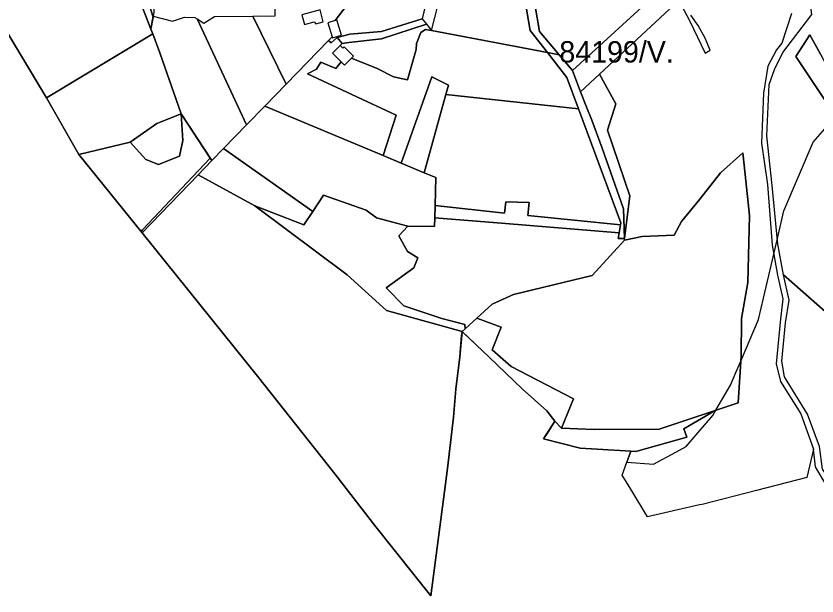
# Model space of a CAD drawing. Extents: x -477304 to -465429, y -1159113 to -1149210.
# Drawn here: x -474702 to -474140, y -1158012 to -1157605 of the extents above; entities that cross this region are included whole.
import ezdxf

# ---------------------------------------------------------------- set-up
doc = ezdxf.new("R2010")
doc.units = 0
for name, color, linetype in [('BPEJ_s', 7, 'Continuous'), ('PUPFL_s', 7, 'Continuous'), ('trav_porost_s', 7, 'Continuous')]:
    doc.layers.add(name, color=color, linetype=linetype)

msp = doc.modelspace()

# ---------------------------------------------------------------- linework, layer by layer
at = {"layer": 'BPEJ_s'}
for p, q in [((-474390.2, -1157843.79), (-474388.88, -1157828.71)), ((-474387.45, -1157827.13), (-474369.68, -1157843.95))]:
    msp.add_line(p, q, dxfattribs=at)
for points in [[(-474712.47, -1157608.26), (-474680.22, -1157661.92), (-474657.54, -1157701.76), (-474613, -1157756.78), (-474613.86, -1157755.71), (-474612.74, -1157754.54), (-474581.44, -1157721.26), (-474565.43, -1157704.24), (-474585.67, -1157673.2), (-474600.56, -1157630.43), (-474605.66, -1157617.09), (-474606.99, -1157613.7), (-474605.39, -1157605.33), (-474610.97, -1157587.24)], [(-474610.97, -1157587.24), (-474605.39, -1157605.33), (-474606.99, -1157613.7), (-474605.66, -1157617.09), (-474600.56, -1157630.43), (-474585.67, -1157673.2), (-474565.43, -1157704.24), (-474581.44, -1157721.26), (-474612.74, -1157754.54), (-474613.86, -1157755.71), (-474613, -1157756.78), (-474532.23, -1157857.36), (-474477.75, -1157925.91), (-474449.03, -1157963.01), (-474410.42, -1158011.51), (-474401.55, -1157943.6), (-474398.88, -1157921.94), (-474394.56, -1157886.06), (-474392.98, -1157866.44), (-474390.2, -1157843.79)], [(-474369.68, -1157843.95), (-474346.33, -1157866.24), (-474329.23, -1157881.6), (-474323.47, -1157888.85), (-474328.97, -1157897.46), (-474331.45, -1157901.34), (-474305.63, -1157907.68), (-474274.04, -1157909.6), (-474270.26, -1157909.83), (-474272.97, -1157917.53), (-474272.96, -1157917.53), (-474254.28, -1157919.03), (-474238.62, -1157910.51), (-474231.42, -1157906.59), (-474222.89, -1157896.69), (-474212.76, -1157884.93), (-474210.52, -1157881.1), (-474200.33, -1157863.66), (-474196.45, -1157854.58), (-474193.11, -1157846.74), (-474180.67, -1157817.53), (-474169.9, -1157771.55), (-474167.35, -1157760.68), (-474162.82, -1157741.31), (-474142.35, -1157693.16), (-474127.51, -1157676.31)], [(-474117.61, -1157959.68), (-474140.54, -1157920.94), (-474142.02, -1157908.41), (-474146.82, -1157928.48), (-474182.11, -1157937.48), (-474220.24, -1157947.2), (-474221.95, -1157947.64), (-474258.41, -1157955.89), (-474270.23, -1157936.46), (-474276.18, -1157926.68), (-474272.97, -1157917.53), (-474272.96, -1157917.53), (-474254.28, -1157919.03), (-474238.62, -1157910.51), (-474231.42, -1157906.59), (-474222.89, -1157896.69), (-474212.76, -1157884.93), (-474210.52, -1157881.1), (-474200.33, -1157863.66), (-474196.45, -1157854.58), (-474193.11, -1157846.74), (-474180.67, -1157817.53), (-474169.9, -1157771.55), (-474167.35, -1157760.68), (-474162.82, -1157741.31), (-474142.35, -1157693.16), (-474127.51, -1157676.31)], [(-474388.88, -1157828.71), (-474388.64, -1157826.01), (-474387.45, -1157827.13)]]:
    msp.add_lwpolyline(points, dxfattribs=at)
at = {"layer": 'PUPFL_s'}
for points in [[(-474712.47, -1157608.26), (-474722.74, -1157590.74), (-474760, -1157522.78), (-474710.53, -1157503.42), (-474659.13, -1157500.47), (-474645.25, -1157520.87), (-474636.26, -1157532.61), (-474626.39, -1157545.34), (-474617.6, -1157586.15), (-474606.99, -1157613.7), (-474605.66, -1157617.09), (-474680.22, -1157661.92)], [(-474607.95, -1157592.56), (-474605.02, -1157592.78), (-474604.85, -1157602.17), (-474605.28, -1157604.75), (-474606.99, -1157613.7), (-474617.6, -1157586.15), (-474626.39, -1157545.34), (-474636.26, -1157532.61), (-474645.25, -1157520.87), (-474633.94, -1157519.44), (-474631.77, -1157529.93), (-474617.59, -1157559.31), (-474616.84, -1157576.89)], [(-474605.66, -1157617.09), (-474600.56, -1157630.43), (-474585.67, -1157673.2), (-474602.64, -1157680.03), (-474621.38, -1157692.95), (-474657.54, -1157701.76), (-474680.22, -1157661.92)], [(-474320.52, -1157631.72), (-474311.11, -1157642.73), (-474305.4, -1157657.64), (-474301.46, -1157667.91), (-474297.65, -1157677.65), (-474290.32, -1157697.33), (-474275.38, -1157739.83), (-474274.67, -1157760.74), (-474278.99, -1157760.63), (-474278.39, -1157756.77), (-474277.5, -1157751.11), (-474277.29, -1157749.76), (-474306.96, -1157669.79), (-474315.19, -1157647.6), (-474328.71, -1157630.16)], [(-474290.32, -1157697.33), (-474297.65, -1157677.65), (-474301.46, -1157667.91), (-474305.4, -1157657.64), (-474292.29, -1157645.45), (-474280.73, -1157666.11), (-474286.53, -1157684.58), (-474270.81, -1157730.79), (-474274.67, -1157760.74), (-474275.38, -1157739.83)], [(-474573.77, -1157715.9), (-474613, -1157756.78), (-474657.54, -1157701.76), (-474621.38, -1157692.95), (-474610.44, -1157705.21), (-474601.68, -1157708.71), (-474586.74, -1157702.98), (-474584.53, -1157691.95), (-474585.67, -1157673.2), (-474564.28, -1157706.01)], [(-474601.68, -1157708.71), (-474610.44, -1157705.21), (-474621.38, -1157692.95), (-474602.64, -1157680.03), (-474585.67, -1157673.2), (-474584.53, -1157691.95), (-474586.74, -1157702.98)], [(-474555.93, -1157697.42), (-474493.38, -1157741.7), (-474499.53, -1157751.13), (-474533.93, -1157737.85), (-474573.77, -1157715.9), (-474564.28, -1157706.01)], [(-474388.64, -1157826.01), (-474390.2, -1157843.79), (-474392.98, -1157866.44), (-474394.56, -1157886.06), (-474398.88, -1157921.94), (-474401.55, -1157943.6), (-474410.42, -1158011.51), (-474449.03, -1157963.01), (-474477.75, -1157925.91), (-474532.23, -1157857.36), (-474613, -1157756.78), (-474573.77, -1157715.9), (-474533.93, -1157737.85), (-474469.31, -1157786.13), (-474441.6, -1157811.16)], [(-474448.65, -1157746.17), (-474426.68, -1157751.96), (-474432.98, -1157758.9), (-474426.97, -1157769.71), (-474419.65, -1157774.16), (-474422.39, -1157781.23), (-474441.83, -1157795.22), (-474429.47, -1157807.85), (-474402.86, -1157816.87), (-474386.7, -1157821.01), (-474386.44, -1157824.02), (-474388.64, -1157826.01), (-474441.6, -1157811.16), (-474469.31, -1157786.13), (-474533.93, -1157737.85), (-474499.53, -1157751.13), (-474493.38, -1157741.7), (-474485.88, -1157730.21), (-474455.86, -1157740.88)], [(-474429.47, -1157807.85), (-474441.83, -1157795.22), (-474422.39, -1157781.23), (-474419.65, -1157774.16), (-474426.97, -1157769.71), (-474432.98, -1157758.9), (-474426.68, -1157751.96), (-474407.92, -1157752.23), (-474407.77, -1157746.14), (-474358.18, -1157750.02), (-474278.39, -1157756.77), (-474278.99, -1157760.63), (-474274.67, -1157760.74), (-474274.63, -1157761.87), (-474297.39, -1157786.66), (-474352.58, -1157799.92), (-474367.39, -1157806.71), (-474378.32, -1157816.64), (-474386.44, -1157824.02), (-474386.7, -1157821.01), (-474402.86, -1157816.87)], [(-474146.32, -1157884.01), (-474162.34, -1157857.62), (-474164.23, -1157846.75), (-474161.58, -1157819.77), (-474159.1, -1157803.83), (-474163.09, -1157786.07), (-474116.35, -1157827.4), (-474076.57, -1157866.3), (-474078.2, -1157867.92), (-474084.04, -1157871.6), (-474096.65, -1157899.23), (-474108.02, -1157917.05), (-474129.83, -1157930.73), (-474135.71, -1157922.41), (-474137.72, -1157906.72)], [(-474318.78, -1157893.66), (-474323.47, -1157888.85), (-474329.23, -1157881.6), (-474346.33, -1157866.24), (-474369.68, -1157843.95), (-474388.64, -1157826.01), (-474386.44, -1157824.02), (-474378.32, -1157816.64), (-474361.24, -1157822.81), (-474367.57, -1157838.77), (-474354.16, -1157850.56), (-474310.37, -1157873.14)]]:
    msp.add_lwpolyline(points, close=True, dxfattribs=at)
at = {"layer": 'trav_porost_s'}
for points in [[(-474533.23, -1157555.32), (-474538.07, -1157546.35), (-474496.57, -1157551.13), (-474489.17, -1157556.62), (-474472.51, -1157534.2), (-474456.92, -1157580.25), (-474477.72, -1157607.65), (-474482.84, -1157609.24), (-474479.8, -1157619.08), (-474482.32, -1157621.67), (-474512.06, -1157652.28), (-474535.44, -1157604.63), (-474519.68, -1157604.47), (-474519.68, -1157601.16), (-474520.38, -1157591.25)], [(-474243.63, -1157580.71), (-474311.11, -1157642.73), (-474320.52, -1157631.72), (-474334.31, -1157615.51), (-474337.55, -1157596.18), (-474318.07, -1157586.58), (-474312.13, -1157583.65), (-474259.5, -1157554.3), (-474255.72, -1157560.12)], [(-474344.66, -1157592.65), (-474340.75, -1157614.65), (-474328.71, -1157630.16), (-474410.07, -1157614.67), (-474400.99, -1157578.93), (-474396.54, -1157574.53), (-474378.86, -1157575.69)], [(-474416.54, -1157606.53), (-474445.16, -1157615.52), (-474467.38, -1157617.23), (-474476.2, -1157619.64), (-474480.45, -1157623.25), (-474482.32, -1157621.67), (-474479.8, -1157619.08), (-474479.57, -1157619.84), (-474473.26, -1157617.9), (-474476.54, -1157607.29), (-474477.72, -1157607.65), (-474456.92, -1157580.25), (-474453.52, -1157591.19), (-474435.77, -1157594.56), (-474427.09, -1157591.16), (-474420.51, -1157583.79), (-474414.77, -1157584.21), (-474410.91, -1157582.73)], [(-474311.11, -1157642.73), (-474243.63, -1157580.71), (-474236.61, -1157593.68), (-474292.29, -1157645.45), (-474305.4, -1157657.64)], [(-474320.52, -1157631.72), (-474328.71, -1157630.16), (-474340.75, -1157614.65), (-474344.66, -1157592.65), (-474337.55, -1157596.18), (-474334.31, -1157615.51)], [(-474500.97, -1157603.64), (-474499.14, -1157610.5), (-474492.28, -1157608.66), (-474491.3, -1157609.96), (-474485.99, -1157608.54), (-474488.22, -1157600.21)], [(-474555.93, -1157697.42), (-474564.28, -1157706.01), (-474585.67, -1157673.2), (-474600.56, -1157630.43), (-474605.66, -1157617.09), (-474606.99, -1157613.7), (-474605.28, -1157604.75), (-474591.86, -1157608.17), (-474583.27, -1157605.28), (-474576.11, -1157605.47), (-474574.45, -1157606.56), (-474539.94, -1157680.97)], [(-474574.45, -1157606.56), (-474569.73, -1157609.66), (-474562.24, -1157604.89), (-474535.44, -1157604.63), (-474512.06, -1157652.28), (-474527.03, -1157667.69), (-474539.94, -1157680.97)], [(-474445.21, -1157620.66), (-474468.12, -1157623.15), (-474472.71, -1157623.9), (-474476.2, -1157619.64), (-474467.38, -1157617.23), (-474445.16, -1157615.52), (-474416.54, -1157606.53), (-474413.5, -1157610.35)], [(-474417.61, -1157616.04), (-474414.16, -1157613.96), (-474410.07, -1157614.67), (-474328.71, -1157630.16), (-474315.19, -1157647.6), (-474306.96, -1157669.79), (-474399.9, -1157659.71), (-474398.04, -1157653.01), (-474409.72, -1157647.18), (-474431.27, -1157707.78), (-474443.97, -1157702.46), (-474434.87, -1157674.21), (-474497.16, -1157645.16), (-474490.76, -1157641.76), (-474487.77, -1157636.89), (-474477.16, -1157641.46), (-474473.46, -1157636.73), (-474471.08, -1157639.1), (-474466.21, -1157634.22), (-474448.12, -1157641.39), (-474436.72, -1157647.16), (-474426.88, -1157649.31), (-474420.8, -1157628.03), (-474420.51, -1157623.91)], [(-474448.12, -1157641.39), (-474466.21, -1157634.22), (-474464.66, -1157632.66), (-474471.21, -1157626.12), (-474472.27, -1157627.18), (-474474.13, -1157625.32), (-474472.71, -1157623.9), (-474468.12, -1157623.15), (-474445.21, -1157620.66), (-474413.5, -1157610.35), (-474410.07, -1157614.67), (-474414.16, -1157613.96), (-474417.61, -1157616.04), (-474420.51, -1157623.91), (-474420.8, -1157628.03), (-474426.88, -1157649.31), (-474436.72, -1157647.16)], [(-474434.87, -1157674.21), (-474443.97, -1157702.46), (-474527.03, -1157667.69), (-474512.06, -1157652.28), (-474482.32, -1157621.67), (-474480.45, -1157623.25), (-474476.2, -1157619.64), (-474472.71, -1157623.9), (-474474.13, -1157625.32), (-474479.5, -1157630.7), (-474473.46, -1157636.73), (-474477.16, -1157641.46), (-474487.77, -1157636.89), (-474490.76, -1157641.76), (-474497.16, -1157645.16)], [(-474119.89, -1157684.92), (-474154.48, -1157632.91), (-474144.56, -1157617.72), (-474137.16, -1157631.38), (-474133.56, -1157637.97), (-474124.43, -1157656.67), (-474112.34, -1157674.57)], [(-474415.13, -1157714.54), (-474431.27, -1157707.78), (-474409.72, -1157647.18), (-474398.04, -1157653.01), (-474399.9, -1157659.71)], [(-474358.86, -1157742.79), (-474407.55, -1157737.55), (-474407.06, -1157717.92), (-474415.13, -1157714.54), (-474399.9, -1157659.71), (-474306.96, -1157669.79), (-474277.29, -1157749.76), (-474277.5, -1157751.11), (-474342.5, -1157744.55), (-474341.54, -1157735.48), (-474357.92, -1157734.92)], [(-474426.68, -1157751.96), (-474448.65, -1157746.17), (-474455.86, -1157740.88), (-474485.88, -1157730.21), (-474493.38, -1157741.7), (-474555.93, -1157697.42), (-474539.94, -1157680.97), (-474527.03, -1157667.69), (-474443.97, -1157702.46), (-474431.27, -1157707.78), (-474415.13, -1157714.54), (-474407.06, -1157717.92), (-474407.55, -1157737.55), (-474407.77, -1157746.14), (-474407.92, -1157752.23)], [(-474191.51, -1157700.53), (-474189.95, -1157715.83), (-474186.94, -1157744.43), (-474188.1, -1157791.55), (-474192.52, -1157816.75), (-474192.88, -1157843.12), (-474195, -1157875.86), (-474210.96, -1157881.25), (-474250.26, -1157894.36), (-474295.83, -1157894.8), (-474318.78, -1157893.66), (-474310.37, -1157873.14), (-474354.16, -1157850.56), (-474367.57, -1157838.77), (-474361.24, -1157822.81), (-474378.32, -1157816.64), (-474367.39, -1157806.71), (-474352.58, -1157799.92), (-474297.39, -1157786.66), (-474274.63, -1157761.87), (-474262.3, -1157759.18), (-474239.75, -1157758.25), (-474234.71, -1157748.63), (-474221.81, -1157733.03), (-474207.23, -1157714.56)], [(-474357.92, -1157734.92), (-474341.54, -1157735.48), (-474342.5, -1157744.55), (-474277.5, -1157751.11), (-474278.39, -1157756.77), (-474358.18, -1157750.02), (-474407.77, -1157746.14), (-474407.55, -1157737.55), (-474358.86, -1157742.79)], [(-474331.45, -1157901.34), (-474323.47, -1157888.85), (-474318.78, -1157893.66), (-474295.83, -1157894.8), (-474250.26, -1157894.36), (-474210.96, -1157881.25), (-474232.92, -1157894.2), (-474230.96, -1157899.96), (-474266.61, -1157910.1), (-474270.26, -1157909.83), (-474305.63, -1157907.68)]]:
    msp.add_lwpolyline(points, close=True, dxfattribs=at)
for points in [[(-474116.35, -1157827.4), (-474163.09, -1157786.07), (-474166.96, -1157764.71), (-474170.98, -1157723.41), (-474174.72, -1157688.58), (-474173.04, -1157652.5), (-474169.41, -1157641.99), (-474163.55, -1157630.22), (-474143.31, -1157603.41), (-474144.71, -1157592.39), (-474149.21, -1157579.62), (-474149.21, -1157552.7), (-474150.25, -1157533.89), (-474131.57, -1157573.47)], [(-474157.5, -1157602.87), (-474164.34, -1157623.53), (-474167.93, -1157628.26), (-474174.15, -1157639.81), (-474177.14, -1157658.61), (-474178.48, -1157693.8), (-474174.4, -1157722.88), (-474170.96, -1157765.26), (-474167.4, -1157786.41), (-474163.55, -1157803.02), (-474165.47, -1157819.45), (-474168.2, -1157848.68), (-474165.18, -1157861.03), (-474150.83, -1157883.73), (-474142.02, -1157908.41), (-474146.82, -1157928.48), (-474182.11, -1157937.48), (-474220.24, -1157947.2), (-474221.95, -1157947.64), (-474258.41, -1157955.89), (-474270.23, -1157936.46), (-474276.18, -1157926.68), (-474270.26, -1157909.83), (-474266.61, -1157910.1), (-474230.96, -1157899.96), (-474232.92, -1157894.2), (-474210.96, -1157881.25), (-474195, -1157875.86), (-474192.88, -1157843.12), (-474192.52, -1157816.75), (-474188.1, -1157791.55), (-474186.94, -1157744.43), (-474189.95, -1157715.83), (-474191.51, -1157700.53), (-474207.23, -1157714.56), (-474221.81, -1157733.03), (-474234.71, -1157748.63), (-474239.75, -1157758.25), (-474262.3, -1157759.18), (-474274.63, -1157761.87), (-474274.67, -1157760.74), (-474270.81, -1157730.79), (-474286.53, -1157684.58), (-474280.73, -1157666.11), (-474292.29, -1157645.45), (-474236.61, -1157593.68), (-474229.03, -1157607.67), (-474218.06, -1157630.5), (-474214.62, -1157628.49), (-474218, -1157620.03), (-474222.9, -1157611.17), (-474228.2, -1157603.96)], [(-474137.16, -1157631.38), (-474144.56, -1157617.72), (-474154.48, -1157632.91), (-474119.89, -1157684.92)]]:
    msp.add_lwpolyline(points, dxfattribs=at)

# ---------------------------------------------------------------- texts
at = {"layer": 'BPEJ_s'}
msp.add_text('84199/V.', height=15, dxfattribs=at).set_placement((-474320.34, -1157637.18))

doc.saveas('drawing.dxf')
